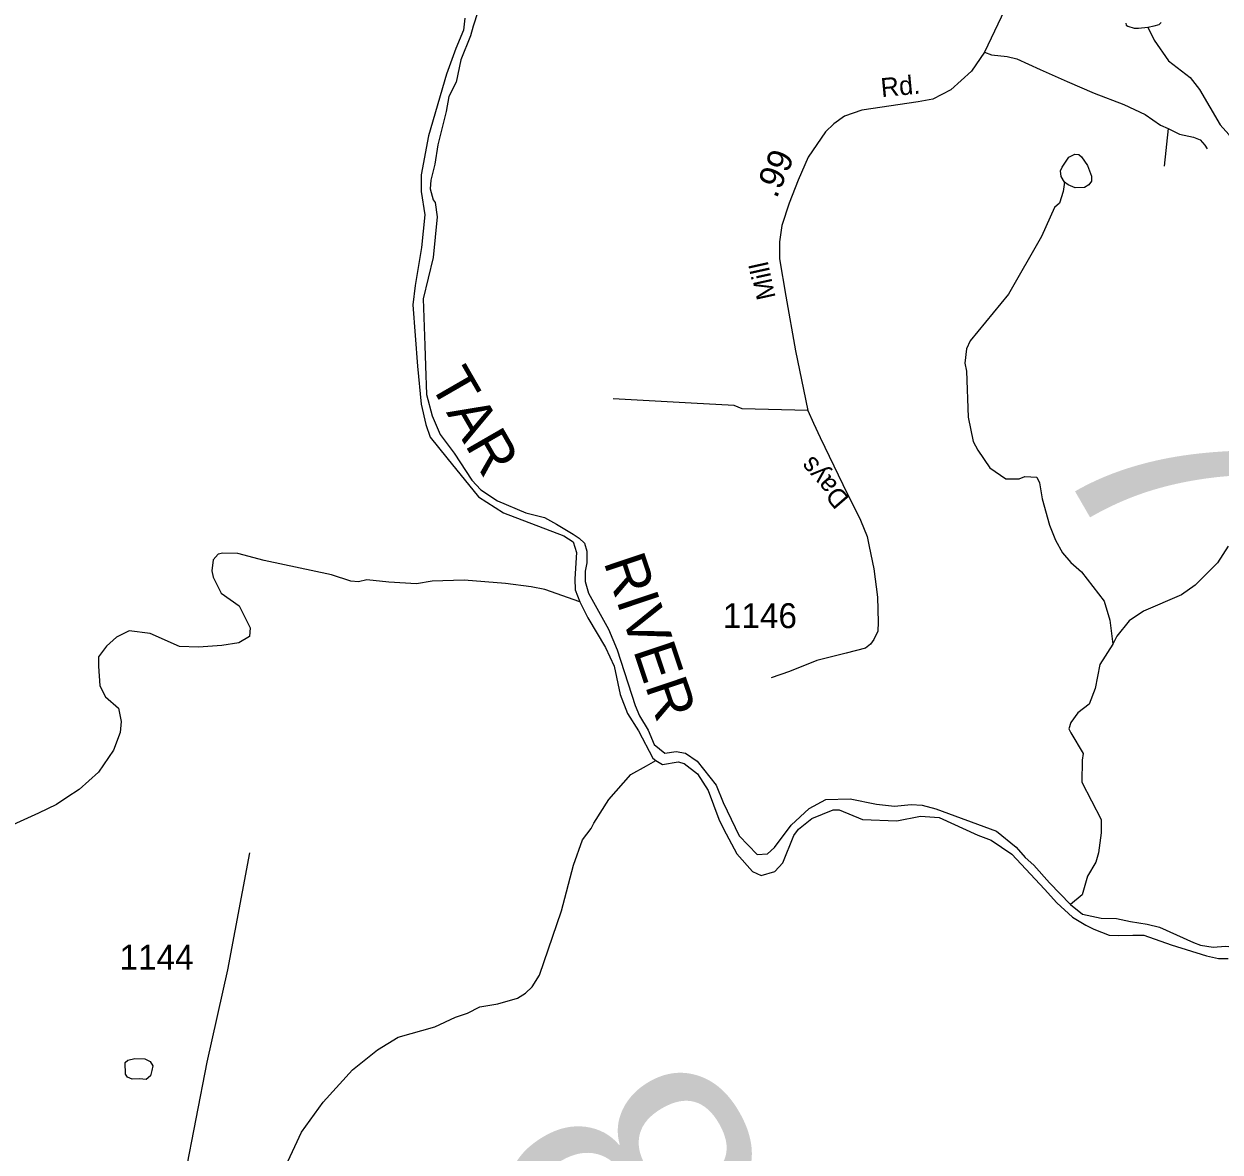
# Model space of a CAD drawing. Extents: x 2056842 to 2160602, y 826753 to 1016856.
# Drawn here: x 2065985 to 2071991, y 933655 to 939319 of the extents above; entities that cross this region are included whole.
import ezdxf

# ---------------------------------------------------------------- set-up
doc = ezdxf.new("R2010")
doc.units = 0
for name, color, linetype in [('Exist Hydrographic Creek Single Shore', 7, 'Continuous'), ('Exist Hydrographic Misc Water Feature', 7, 'Continuous'), ('Exist Hydrographic River Shore', 7, 'Continuous'), ('Exist Hydrographic River Shore Label', 7, 'Continuous'), ('Exist Road Non-System Type 51', 7, 'Continuous'), ('Exist Road Secondary Mileage Hundredths English Label', 7, 'Continuous'), ('Exist Road Secondary Structure Standard Bridge Number Label', 7, 'Continuous'), ('Exist Road Secondary Type 51 Attributed', 7, 'Continuous'), ('Exist Road Secondary Type 51 Label', 7, 'Continuous'), ('Exist Road Secondary Type 51 Number Label', 7, 'Continuous')]:
    doc.layers.add(name, color=color, linetype=linetype)

msp = doc.modelspace()

# ---------------------------------------------------------------- linework, layer by layer
at = {"layer": 'Exist Hydrographic Creek Single Shore'}
msp.add_lwpolyline([(2068776.4, 936417.3), (2068600.5, 936478.2), (2068532.4, 936492.7), (2068403.4, 936508.6), (2068194.8, 936526), (2068034, 936520.2), (2067955.7, 936507.2), (2067816.6, 936515.9), (2067707.4, 936527.5), (2067665.4, 936517.3), (2067626.3, 936521.7), (2067529.2, 936552.1), (2067191.7, 936625.2), (2067058.6, 936659.4), (2066983.4, 936660.7), (2066959.7, 936656.6), (2066935.5, 936628.5), (2066927.8, 936572.6), (2066935.6, 936540.6), (2066976, 936460.7), (2067065.8, 936397), (2067120.9, 936286.8), (2067118, 936243.3), (2067064.4, 936211.4), (2066978.9, 936198.4), (2066861, 936189.7), (2066765.3, 936192.6), (2066619, 936257.8), (2066513.2, 936270.9), (2066449.5, 936240.4), (2066400.2, 936194), (2066358.8, 936141.8), (2066358.8, 936094), (2066366, 935995.4), (2066395, 935940.3), (2066460.2, 935883.8), (2066473.2, 935815.6), (2066468.9, 935760.5), (2066434.1, 935672.8), (2066360.2, 935561.2), (2066261.7, 935474.2), (2066200.8, 935435.1), (2066148.7, 935400.3), (2066058.9, 935355.3), (2065892.8, 935280.7)], dxfattribs=at)
at = {"layer": 'Exist Hydrographic Misc Water Feature'}
for points in [[(2071517.1, 939321.9), (2071520, 939313.2), (2071528.7, 939307.4), (2071559.1, 939297.2), (2071580.8, 939297.2), (2071628.6, 939301.6)], [(2071628.6, 939301.6), (2071660.5, 939308.8), (2071685.1, 939316.1), (2071695.3, 939326.2)], [(2071628.6, 939301.6), (2071660.7, 939237.5), (2071732.9, 939133.6), (2071841.1, 939049.9), (2071887.3, 938989.9), (2071991.4, 938812.1), (2072035.5, 938764.2), (2072079.6, 938728.3), (2072155.7, 938684.5), (2072257.8, 938648.6), (2072439.9, 938559), (2072601.9, 938503.3), (2072704, 938451.5)], [(2071209.9, 938524.5), (2071192.5, 938552.1), (2071189.6, 938581), (2071198.3, 938599.9), (2071231.7, 938649.2), (2071262.1, 938665.1), (2071282.4, 938663.7), (2071295.4, 938652.1), (2071325.8, 938608.6), (2071346.1, 938555), (2071346.1, 938528.9), (2071331.6, 938510), (2071309.9, 938497), (2071263.5, 938495.5), (2071228.8, 938510), (2071209.9, 938524.5)], [(2071209.9, 938524.5), (2071204, 938476.7), (2071184.1, 938418.6), (2071160.4, 938396.6), (2071094.5, 938250.6), (2070929.1, 937962.2), (2070735.7, 937727.8), (2070717.6, 937687.8), (2070709.6, 937615.8), (2070717.8, 937575.8), (2070726.3, 937343.8), (2070750.5, 937221.9), (2070774.6, 937177.9), (2070834.7, 937090.1), (2070914.9, 937034.2), (2070982.8, 937034.3), (2071010.7, 937046.4), (2071070.7, 937042.5), (2071084.9, 937014.5), (2071097, 936934.5), (2071135.1, 936802.6), (2071165.3, 936726.7), (2071199.5, 936662.7), (2071241.6, 936614.8), (2071295.7, 936566.9), (2071409.9, 936421.1), (2071438.2, 936325.2), (2071452.3, 936205.3)], [(2072031.4, 936696.3), (2071977.5, 936612.2), (2071865.7, 936500), (2071797.9, 936451.8), (2071605.9, 936369.5), (2071534.2, 936321.3), (2071472.2, 936245.3), (2071452.3, 936205.3)], [(2071452.3, 936205.3), (2071387.8, 936102.7), (2071363.2, 935982.4), (2071334.2, 935904.1), (2071276.3, 935859.1), (2071241.1, 935810.9), (2071231.1, 935778.8), (2071241.1, 935758.9), (2071303.3, 935655), (2071299.4, 935623), (2071297.5, 935511), (2071393.6, 935324.9), (2071393.6, 935256.8), (2071380.7, 935157.1), (2071366.7, 935109.9), (2071325.9, 935039.7), (2071299.1, 934946.6), (2071240.5, 934896.9)], [(2067299.4, 933585.6), (2067379, 933753.8), (2067486.8, 933905.9), (2067634.5, 934068.2), (2067760.2, 934168.5), (2067864.1, 934230.6), (2068048.1, 934283), (2068151.8, 934331.2), (2068211.9, 934351.3), (2068273.8, 934383.4), (2068363.9, 934399.6), (2068463.7, 934427.8), (2068503.7, 934451.8), (2068537.5, 934483.9), (2068573.4, 934541.9), (2068685, 934866.1), (2068744.4, 935094.2), (2068790.2, 935222.4), (2068834, 935278.3), (2068846.1, 935306.4), (2068921.8, 935424.5), (2069031.7, 935550.3), (2069111.7, 935592.9), (2069157.7, 935619.9)], [(2066565.5, 934022.8), (2066528.5, 934020.9), (2066505.1, 934030.6), (2066495.3, 934046.2), (2066493.4, 934104.7), (2066507, 934116.4), (2066542.1, 934124.2), (2066592.8, 934122.3), (2066618.1, 934108.6), (2066631.7, 934087.2), (2066627.8, 934063.8), (2066620, 934036.5), (2066598.6, 934018.9), (2066565.5, 934022.8)]]:
    msp.add_lwpolyline(points, dxfattribs=at)
at = {"layer": 'Exist Hydrographic River Shore'}
for points in [[(2068264.4, 939379.1), (2068240.6, 939307), (2068226.8, 939259.1), (2068179, 939139), (2068155, 939026.9), (2068119.1, 938954.8), (2068105.3, 938879.7), (2068063.8, 938710.8), (2068047.7, 938614.7), (2068028, 938534.7), (2068024.1, 938490.5), (2068040.1, 938434.7), (2068050.3, 938422.7), (2068060.3, 938349.8), (2068040.6, 938146.6), (2067989.1, 937938.6), (2067998, 937704), (2068001.8, 937602.7), (2068006, 937458.5), (2068034.3, 937350.6), (2068074.4, 937256.6), (2068144.6, 937163), (2068234.6, 937027.2), (2068278.9, 936979), (2068363.1, 936923.5), (2068504.9, 936863.4), (2068599.3, 936839.8), (2068659.3, 936807.7), (2068743.2, 936756.1), (2068772.9, 936736.2), (2068799, 936711.6), (2068811.4, 936672), (2068811.4, 936612.3), (2068803.3, 936571), (2068803.3, 936518.8), (2068819.8, 936460.2), (2068920.1, 936280.3), (2068964.2, 936176.3), (2069054.8, 935896.5), (2069075.1, 935844.5), (2069119.2, 935772.8), (2069149.2, 935700.9), (2069203.1, 935656.8), (2069259.4, 935665.2), (2069307.1, 935657), (2069365.4, 935617.4), (2069461.6, 935497.2), (2069496.8, 935409.7), (2069576.4, 935241.5), (2069666, 935147.8), (2069718.3, 935152), (2069754.1, 935184), (2069837.8, 935296.2), (2069927.8, 935380.3), (2070011.7, 935424.5), (2070133.6, 935428.5), (2070265.8, 935401.7), (2070357.1, 935391.6), (2070439.8, 935399.2), (2070495.8, 935395.4), (2070563.7, 935377.6), (2070867.8, 935265.9), (2070967.9, 935186.1), (2071012.1, 935134.3), (2071056.2, 935094.4), (2071134.5, 935006.4), (2071240.5, 934896.9)], [(2068198.8, 939347.1), (2068192.8, 939287.1), (2068153.1, 939195.8), (2068107.1, 939066.9), (2068015.7, 938756.8), (2067980.2, 938560.7), (2067980.4, 938476.7), (2067998.4, 938360.8), (2067980.7, 938196.1), (2067949.2, 938004.6), (2067937.3, 937908.6), (2067960.4, 937599.6), (2067979.2, 937409.7), (2068003.8, 937308.2), (2068025.6, 937244.4), (2068108.2, 937140), (2068268.1, 936943.9), (2068393.2, 936863.5), (2068695.4, 936748), (2068743.4, 936718.2), (2068759.6, 936664.2), (2068751.8, 936532.2), (2068752.6, 936476.7), (2068776.4, 936417.3)], [(2068776.4, 936417.3), (2068816.9, 936337.6), (2068905.3, 936188.2), (2068948.7, 936094.5), (2068978.8, 935952.6), (2069015.1, 935856.7), (2069071.3, 935768.8), (2069143.5, 935633), (2069157.7, 935619.9)], [(2069157.7, 935619.9), (2069191.4, 935601.1), (2069269.6, 935613.2), (2069299.5, 935605.3), (2069367.6, 935553.4), (2069421.4, 935470.6), (2069475, 935325.6), (2069498.2, 935277.6), (2069564, 935152.4), (2069643.7, 935062.5), (2069687.1, 935043.6), (2069755.2, 935063.9), (2069795.8, 935107.4), (2069850.1, 935244.3), (2069874.1, 935276.3), (2069941.9, 935328.5), (2070047.9, 935372.7), (2070078.9, 935372.7), (2070194.8, 935324.9), (2070367.2, 935317.6), (2070487.5, 935340.8), (2070580.2, 935333.6), (2070774, 935245.9), (2070841.9, 935220.5), (2070944.8, 935150.9), (2071108.7, 934974.7), (2071170.8, 934906.7), (2071249.4, 934833.1), (2071316.8, 934793.6), (2071357.7, 934774.4), (2071434.9, 934743.3), (2071482.7, 934741.3), (2071552.8, 934743.2), (2071607.6, 934743.8), (2071746, 934694.7), (2071922.5, 934639.2), (2071983.1, 934625.8), (2072032, 934626.1)], [(2071240.5, 934896.9), (2071300.4, 934849.7), (2071394.7, 934829.3), (2071471.2, 934826.7), (2071541.3, 934811.4), (2071624.7, 934799.4), (2071686.6, 934783.4), (2071857, 934706), (2071892.6, 934693.4), (2071956.7, 934682.7), (2072018.8, 934688.2), (2072100.7, 934679.8), (2072142.8, 934656.4), (2072181, 934616.6), (2072222.7, 934446), (2072268.6, 934319.7), (2072373.1, 934146.3), (2072478.1, 934050.9), (2072514.2, 934023.3), (2072612.2, 933999.3), (2072803.2, 934014.9), (2072875.9, 934025.1), (2072944.7, 934017.4), (2072991.9, 934012.3)]]:
    msp.add_lwpolyline(points, dxfattribs=at)
at = {"layer": 'Exist Road Non-System Type 51'}
msp.add_line((2071731.2, 938793.7), (2071711, 938604.1), dxfattribs=at)
for points in [[(2070807.5, 939176.5), (2070842.7, 939162.6), (2070922.8, 939155.2), (2070969.9, 939142.7), (2071087.1, 939090.6), (2071224.1, 939028.8), (2071359, 938970.8), (2071507.1, 938914.2), (2071615.5, 938863.5), (2071692.3, 938809.8), (2071731.2, 938793.7)], [(2071731.2, 938793.7), (2071787.4, 938764.3), (2071858, 938749.6), (2071890.3, 938736.3), (2071913.8, 938709.9), (2071927, 938690.8)], [(2069921.6, 937377.6), (2069590.6, 937385.8), (2069550.6, 937403.4), (2069334.7, 937414.6), (2068943.8, 937437)]]:
    msp.add_lwpolyline(points, dxfattribs=at)
at = {"layer": 'Exist Road Secondary Type 51 Attributed'}
for points in [[(2070907.8, 939388.2), (2070807.5, 939176.5), (2070742.4, 939081), (2070639.5, 938986.9), (2070549.2, 938941.4), (2070474.6, 938926.9), (2070192.7, 938885.5), (2070106, 938856.1), (2070051.7, 938816.4), (2070010.5, 938776.1), (2069923.1, 938650.4), (2069873.1, 938534.3), (2069826.8, 938418.1), (2069790.8, 938306.4), (2069778.3, 938224.1), (2069778.3, 938187.4), (2069778.6, 938139.2), (2069811.4, 937952.2), (2069859.4, 937676.8), (2069899.5, 937483.4), (2069921.6, 937377.6), (2069948.8, 937314.4), (2069982.6, 937242.4), (2070096.4, 937006.7), (2070186.4, 936826.3), (2070219.1, 936744.7), (2070228.7, 936694.3), (2070253, 936582.4), (2070270.6, 936441.3), (2070275.1, 936314.9), (2070272.1, 936269.4), (2070253, 936228.2), (2070235.4, 936204.7), (2070210.3, 936184.7), (2070112.8, 936159.1), (2069966.9, 936122.7), (2069829.4, 936066.6), (2069736.7, 936036)], [(2066982.3, 930791.8), (2066937.4, 931093.7), (2066883.5, 931395.6), (2066847.6, 931546.5), (2066815.7, 931656.1), (2066765, 931765.7), (2066626.8, 932159.2), (2066594.4, 932303), (2066594.4, 932450.3), (2066616, 932665.9), (2066684.2, 932967.8), (2066905.1, 934105.2), (2067009.2, 934568.8), (2067118.8, 935156.4)]]:
    msp.add_lwpolyline(points, dxfattribs=at)

# ---------------------------------------------------------------- texts
at = {"layer": 'Exist Hydrographic River Shore Label'}
for s, rotation, p in [('TAR', 299.96009, (2068017.8, 937516.8)), ('RIVER', 288.53473, (2068894, 936617.8))]:
    msp.add_text(s, height=210, rotation=rotation, dxfattribs=at).set_placement(p)
at = {"layer": 'Exist Road Secondary Mileage Hundredths English Label'}
msp.add_text('.99', height=125, rotation=66.71394, dxfattribs=at).set_placement((2069763.8, 938438.5))
at = {"layer": 'Exist Road Secondary Structure Standard Bridge Number Label'}
for s, height, p in [('7', 1230.3, (2071116.2, 937225.8)), ('84', 1230.31, (2068267.5, 933626.2))]:
    msp.add_text(s, height=height, rotation=300, dxfattribs=at).set_placement(p)
at = {"layer": 'Exist Road Secondary Type 51 Label'}
for s, rotation, p in [('Rd.', 5.39385, (2070291.7, 938950.8)), ('Mill', 102.44125, (2069760.1, 937945.2)), ('Days', 130.89788, (2070134.3, 936936.8))]:
    msp.add_text(s, height=95, rotation=rotation, dxfattribs=at).set_placement(p)
at = {"layer": 'Exist Road Secondary Type 51 Number Label'}
for s, p in [('1146', (2069494.6, 936285.1)), ('1144', (2066465.1, 934570.3))]:
    msp.add_text(s, height=125, dxfattribs=at).set_placement(p)

doc.saveas('drawing.dxf')
